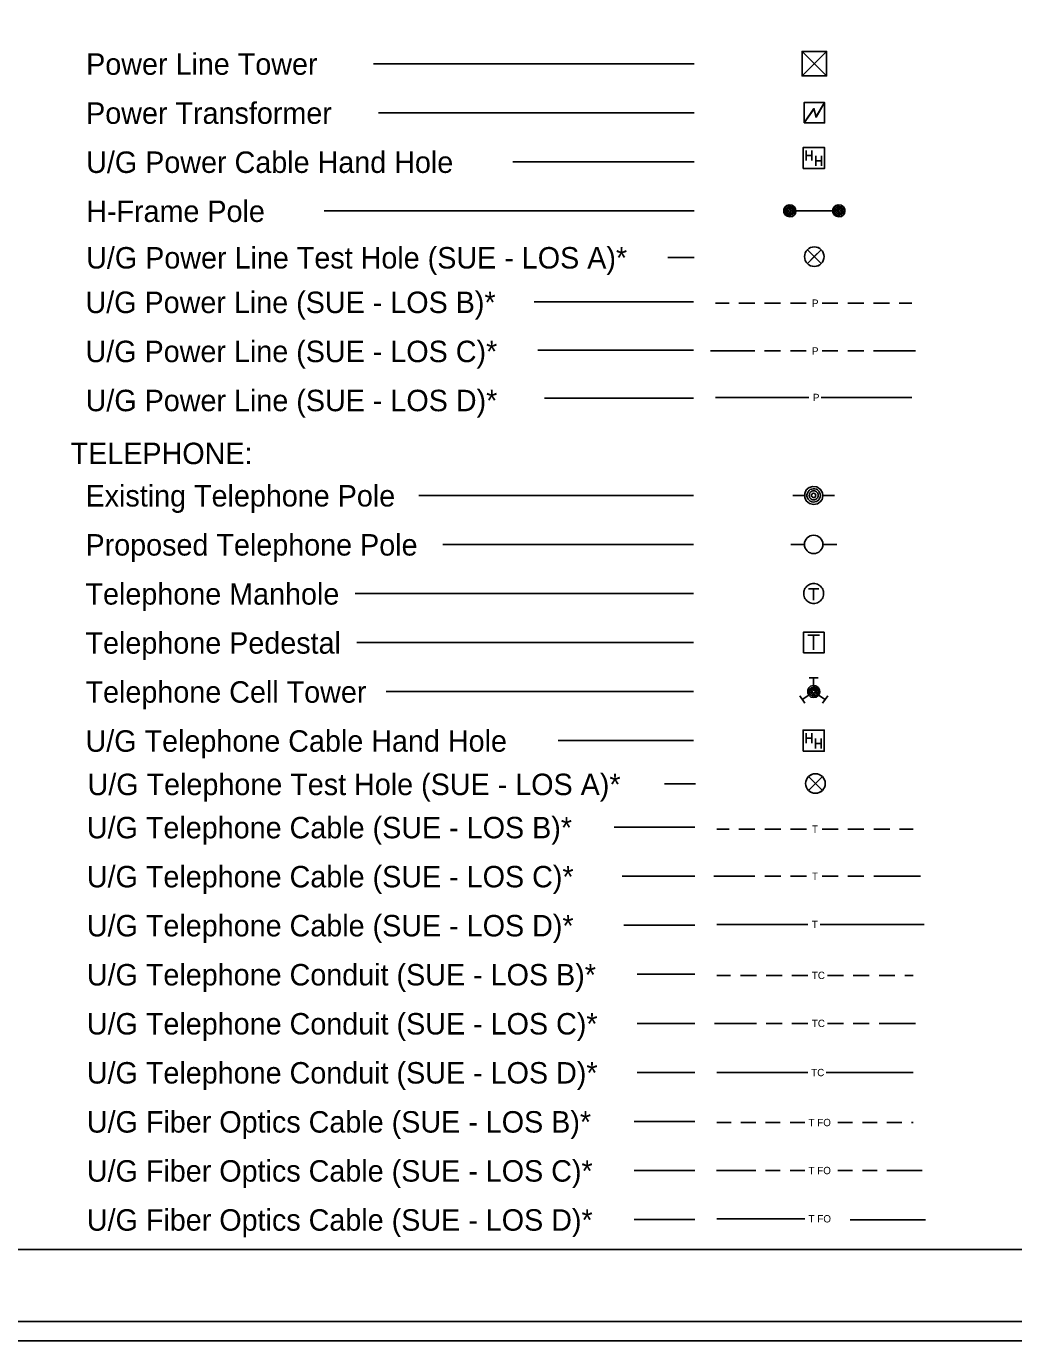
# Model space of a CAD drawing. Extents: x 811137 to 813186, y 647386 to 648494.
# Drawn here: x 812004 to 812410, y 647386 to 647927 of the extents above; entities that cross this region are included whole.
import ezdxf

# ---------------------------------------------------------------- set-up
doc = ezdxf.new("R2010")
doc.units = 0
for name, color, linetype in [('Default', 7, 'Continuous'), ('Exist Utilities Power Test Hole SUE LOS A CELL', 7, 'Continuous'), ('Exist Utilities Telephone Test Hole SUE LOS A CELL', 7, 'Continuous'), ('Sheet_Plan', 7, 'Continuous'), ('Sheet_Symbology', 7, 'Continuous'), ('z - Construction', 7, 'Continuous')]:
    doc.layers.add(name, color=color, linetype=linetype)

msp = doc.modelspace()

# ---------------------------------------------------------------- linework, layer by layer
at = {"layer": 'Default'}
msp.add_lwpolyline([(812820.63, 648494.02), (811136.63, 648494.02), (811136.63, 647394.02), (812820.63, 647394.02)], close=True, dxfattribs=at)
at = {"layer": 'Exist Utilities Power Test Hole SUE LOS A CELL'}
for points in [[(812330.92, 647834.94), (812325.21, 647829.24), (812328.07, 647832.09), (812325.21, 647834.94), (812330.92, 647829.24)], [(812325.21, 647834.94), (812328.07, 647832.09), (812330.92, 647834.94)], [(812330.92, 647829.24), (812328.07, 647832.09), (812325.21, 647829.24)]]:
    msp.add_lwpolyline(points, dxfattribs=at)
msp.add_circle((812328.07, 647832.09), 4.03, dxfattribs=at)
for start, end in [(45, 135), (225, 315)]:
    msp.add_arc((812328.07, 647832.09), 4.03, start, end, dxfattribs=at)
at = {"layer": 'Exist Utilities Telephone Test Hole SUE LOS A CELL'}
for points in [[(812331.39, 647618.17), (812325.69, 647612.47), (812328.54, 647615.32), (812325.69, 647618.17), (812331.39, 647612.47)], [(812325.69, 647618.17), (812328.54, 647615.32), (812331.39, 647618.17)], [(812331.39, 647612.47), (812328.54, 647615.32), (812325.69, 647612.47)]]:
    msp.add_lwpolyline(points, dxfattribs=at)
msp.add_circle((812328.54, 647615.32), 4.03, dxfattribs=at)
for start, end in [(45, 135), (225, 315)]:
    msp.add_arc((812328.54, 647615.32), 4.03, start, end, dxfattribs=at)
at = {"layer": 'Sheet_Plan'}
msp.add_line((811178.28, 647423.58), (812803.25, 647423.58), dxfattribs=at)
at = {"layer": 'Sheet_Symbology'}
for p, q in [((812333.15, 647916.53), (812323.08, 647906.45)), ((812333.15, 647906.45), (812323.08, 647916.53)), ((812278.64, 647911.46), (812146.8, 647911.46)), ((812278.64, 647891.28), (812148.85, 647891.28)), ((812324.79, 647875.74), (812324.79, 647871.67)), ((812327.11, 647875.74), (812327.11, 647871.67)), ((812278.64, 647871.1), (812204.09, 647871.1)), ((812324.79, 647873.66), (812327.11, 647873.66)), ((812328.67, 647873.52), (812328.67, 647869.46)), ((812328.67, 647871.45), (812330.99, 647871.45)), ((812330.99, 647873.52), (812330.99, 647869.46)), ((812278.64, 647850.93), (812126.6, 647850.93)), ((812318, 647850.93), (812338.18, 647850.93)), ((812278.64, 647831.78), (812267.91, 647831.78)), ((812278.36, 647813.45), (812212.86, 647813.45)), ((812287.46, 647812.96), (812293.01, 647812.96)), ((812297.04, 647812.96), (812303.6, 647812.96)), ((812307.64, 647812.96), (812314.19, 647812.96)), ((812318.23, 647812.96), (812324.79, 647812.96)), ((812331.24, 647812.96), (812337.8, 647812.96)), ((812341.84, 647812.96), (812348.4, 647812.96)), ((812352.43, 647812.96), (812358.99, 647812.96)), ((812363.03, 647812.96), (812368.17, 647812.96)), ((812278.36, 647793.66), (812214.42, 647793.66)), ((812285.42, 647793.27), (812303.6, 647793.27)), ((812307.64, 647793.27), (812314.19, 647793.27)), ((812318.23, 647793.27), (812324.79, 647793.27)), ((812331.24, 647793.27), (812337.8, 647793.27)), ((812341.84, 647793.27), (812348.4, 647793.27)), ((812352.43, 647793.27), (812369.61, 647793.27)), ((812278.36, 647773.86), (812217.13, 647773.86)), ((812287.46, 647774.14), (812325.88, 647774.14)), ((812330.93, 647774.14), (812368.17, 647774.14)), ((812278.36, 647733.86), (812165.48, 647733.86)), ((812324.09, 647733.86), (812319.25, 647733.86)), ((812331.54, 647733.86), (812336.38, 647733.86)), ((812278.36, 647713.68), (812175.39, 647713.68)), ((812324.07, 647713.67), (812318.39, 647713.67)), ((812331.64, 647713.67), (812337.31, 647713.67)), ((812278.36, 647693.5), (812139.27, 647693.5)), ((812329.91, 647695.4), (812325.75, 647695.4)), ((812327.81, 647695.4), (812327.81, 647690.81)), ((812325.45, 647676.36), (812330.17, 647676.36)), ((812327.81, 647670.28), (812327.81, 647676.36)), ((812278.36, 647673.32), (812139.97, 647673.32)), ((812325.92, 647658.85), (812329.71, 647658.85)), ((812327.81, 647655.63), (812327.81, 647658.85)), ((812278.36, 647653.14), (812152.02, 647653.14)), ((812324.23, 647648.32), (812322.06, 647651.42)), ((812325.79, 647651.72), (812323.14, 647649.87)), ((812329.85, 647651.73), (812332.49, 647649.88)), ((812333.58, 647651.43), (812331.41, 647648.33)), ((812278.36, 647632.97), (812222.83, 647632.97)), ((812324.72, 647636.02), (812324.72, 647631.95)), ((812324.72, 647633.95), (812327.04, 647633.95)), ((812327.04, 647636.02), (812327.04, 647631.95)), ((812328.6, 647633.8), (812328.6, 647629.74)), ((812330.93, 647633.8), (812330.93, 647629.74)), ((812328.6, 647631.73), (812330.93, 647631.73)), ((812279.19, 647615.13), (812266.42, 647615.13)), ((812278.91, 647597.35), (812245.84, 647597.35)), ((812288.01, 647596.55), (812293.08, 647596.55)), ((812297.11, 647596.55), (812303.67, 647596.55)), ((812307.71, 647596.55), (812314.27, 647596.55)), ((812318.3, 647596.55), (812324.86, 647596.55)), ((812331.32, 647596.55), (812337.87, 647596.55)), ((812341.91, 647596.55), (812348.47, 647596.55)), ((812352.5, 647596.55), (812359.06, 647596.55)), ((812363.1, 647596.55), (812368.72, 647596.55)), ((812278.91, 647577.17), (812249.03, 647577.17)), ((812286.75, 647577.17), (812303.67, 647577.17)), ((812307.71, 647577.17), (812314.27, 647577.17)), ((812318.3, 647577.17), (812324.86, 647577.17)), ((812331.32, 647577.17), (812337.87, 647577.17)), ((812341.91, 647577.17), (812348.47, 647577.17)), ((812352.5, 647577.17), (812371.71, 647577.17)), ((812278.91, 647556.99), (812249.8, 647556.99)), ((812288.01, 647557.35), (812325.46, 647557.35)), ((812330.51, 647557.35), (812373.27, 647557.35)), ((812278.91, 647536.82), (812255.24, 647536.82)), ((812288.01, 647536.38), (812293.64, 647536.38)), ((812297.68, 647536.38), (812304.24, 647536.38)), ((812308.27, 647536.38), (812314.83, 647536.38)), ((812318.87, 647536.38), (812325.43, 647536.38)), ((812333.5, 647536.38), (812340.06, 647536.38)), ((812344.09, 647536.38), (812350.65, 647536.38)), ((812354.69, 647536.38), (812361.24, 647536.38)), ((812365.28, 647536.38), (812368.72, 647536.38)), ((812278.91, 647516.64), (812255.24, 647516.64)), ((812287.05, 647516.64), (812304.24, 647516.64)), ((812308.27, 647516.64), (812314.83, 647516.64)), ((812318.87, 647516.64), (812325.43, 647516.64)), ((812333.5, 647516.64), (812340.06, 647516.64)), ((812344.09, 647516.64), (812350.65, 647516.64)), ((812354.69, 647516.64), (812369.69, 647516.64)), ((812278.91, 647496.46), (812255.24, 647496.46)), ((812288.01, 647496.41), (812325.43, 647496.41)), ((812332.99, 647496.41), (812368.72, 647496.41)), ((812278.91, 647476.28), (812254.07, 647476.28)), ((812288.01, 647475.84), (812293.9, 647475.84)), ((812297.93, 647475.84), (812303.99, 647475.84)), ((812308.02, 647475.84), (812314.08, 647475.84)), ((812318.11, 647475.84), (812324.17, 647475.84)), ((812337.79, 647475.84), (812343.84, 647475.84)), ((812347.88, 647475.84), (812353.93, 647475.84)), ((812357.96, 647475.84), (812364.02, 647475.84)), ((812368.05, 647475.84), (812368.72, 647475.84)), ((812278.91, 647456.1), (812254.07, 647456.1)), ((812287.82, 647456.1), (812303.99, 647456.1)), ((812308.02, 647456.1), (812314.08, 647456.1)), ((812318.11, 647456.1), (812324.17, 647456.1)), ((812337.79, 647456.1), (812343.84, 647456.1)), ((812347.88, 647456.1), (812353.93, 647456.1)), ((812357.96, 647456.1), (812372.41, 647456.1)), ((812278.91, 647435.92), (812254.07, 647435.92)), ((812288.01, 647436.25), (812324.2, 647436.25)), ((812342.87, 647435.86), (812373.77, 647435.86))]:
    msp.add_line(p, q, dxfattribs=at)
for points in [[(812333.15, 647906.45), (812323.08, 647906.45), (812323.08, 647916.53), (812333.15, 647916.53), (812333.15, 647906.45), (812323.08, 647906.45), (812323.08, 647916.53), (812333.15, 647916.53), (812333.15, 647906.45)], [(812323.88, 647887.08), (812327.86, 647892.79), (812328.82, 647889.68), (812332.29, 647895.49)], [(812323.88, 647887.08), (812327.89, 647893.02), (812328.79, 647889.45), (812332.29, 647895.49)], [(812323.88, 647887.08), (812332.29, 647887.08), (812332.29, 647895.49), (812323.88, 647895.49), (812323.88, 647887.08)], [(812323.54, 647868.34), (812332.22, 647868.34), (812332.22, 647877.03), (812323.54, 647877.03), (812323.54, 647868.34)], [(812319.84, 647850.93), (812319.79, 647851.37), (812319.64, 647851.77), (812319.39, 647852.12), (812319.09, 647852.41), (812318.75, 647852.61), (812318.3, 647852.71), (812317.9, 647852.76), (812317.45, 647852.66), (812317.06, 647852.51), (812316.76, 647852.27), (812316.46, 647851.92), (812316.26, 647851.57), (812316.16, 647851.12), (812316.16, 647850.73), (812316.26, 647850.28), (812316.46, 647849.93), (812316.76, 647849.58), (812317.06, 647849.34), (812317.45, 647849.19), (812317.9, 647849.09), (812318.3, 647849.14), (812318.75, 647849.24), (812319.09, 647849.44), (812319.39, 647849.73), (812319.64, 647850.08), (812319.79, 647850.48), (812319.84, 647850.93)], [(812319.24, 647850.93), (812319.19, 647851.27), (812319.04, 647851.62), (812318.79, 647851.87), (812318.5, 647852.07), (812318.2, 647852.17), (812317.8, 647852.17), (812317.5, 647852.07), (812317.21, 647851.87), (812316.96, 647851.62), (812316.81, 647851.27), (812316.76, 647850.93), (812316.81, 647850.58), (812316.96, 647850.23), (812317.21, 647849.98), (812317.5, 647849.78), (812317.8, 647849.68), (812318.2, 647849.68), (812318.5, 647849.78), (812318.79, 647849.98), (812319.04, 647850.23), (812319.19, 647850.58), (812319.24, 647850.93)], [(812318.6, 647850.93), (812318.55, 647851.17), (812318.4, 647851.37), (812318.2, 647851.47), (812317.95, 647851.52), (812317.7, 647851.42), (812317.5, 647851.27), (812317.4, 647851.03), (812317.4, 647850.83), (812317.5, 647850.58), (812317.7, 647850.43), (812317.95, 647850.33), (812318.2, 647850.38), (812318.4, 647850.48), (812318.55, 647850.68), (812318.6, 647850.93)], [(812340.02, 647850.93), (812339.97, 647851.37), (812339.82, 647851.77), (812339.57, 647852.12), (812339.27, 647852.41), (812338.92, 647852.61), (812338.48, 647852.71), (812338.08, 647852.76), (812337.63, 647852.66), (812337.24, 647852.51), (812336.94, 647852.27), (812336.64, 647851.92), (812336.44, 647851.57), (812336.34, 647851.12), (812336.34, 647850.73), (812336.44, 647850.28), (812336.64, 647849.93), (812336.94, 647849.58), (812337.24, 647849.34), (812337.63, 647849.19), (812338.08, 647849.09), (812338.48, 647849.14), (812338.92, 647849.24), (812339.27, 647849.44), (812339.57, 647849.73), (812339.82, 647850.08), (812339.97, 647850.48), (812340.02, 647850.93)], [(812339.42, 647850.93), (812339.37, 647851.27), (812339.22, 647851.62), (812338.97, 647851.87), (812338.68, 647852.07), (812338.38, 647852.17), (812337.98, 647852.17), (812337.68, 647852.07), (812337.38, 647851.87), (812337.14, 647851.62), (812336.99, 647851.27), (812336.94, 647850.93), (812336.99, 647850.58), (812337.14, 647850.23), (812337.38, 647849.98), (812337.68, 647849.78), (812337.98, 647849.68), (812338.38, 647849.68), (812338.68, 647849.78), (812338.97, 647849.98), (812339.22, 647850.23), (812339.37, 647850.58), (812339.42, 647850.93)], [(812338.77, 647850.93), (812338.73, 647851.17), (812338.58, 647851.37), (812338.38, 647851.47), (812338.13, 647851.52), (812337.88, 647851.42), (812337.68, 647851.27), (812337.58, 647851.03), (812337.58, 647850.83), (812337.68, 647850.58), (812337.88, 647850.43), (812338.13, 647850.33), (812338.38, 647850.38), (812338.58, 647850.48), (812338.73, 647850.68), (812338.77, 647850.93)], [(812330.57, 647733.86), (812330.49, 647734.53), (812330.27, 647735.12), (812329.9, 647735.65), (812329.45, 647736.09), (812328.93, 647736.39), (812328.26, 647736.54), (812327.66, 647736.62), (812326.99, 647736.47), (812326.4, 647736.24), (812325.95, 647735.87), (812325.51, 647735.35), (812325.21, 647734.83), (812325.06, 647734.16), (812325.06, 647733.56), (812325.21, 647732.89), (812325.51, 647732.37), (812325.95, 647731.85), (812326.4, 647731.48), (812326.99, 647731.25), (812327.66, 647731.1), (812328.26, 647731.18), (812328.93, 647731.33), (812329.45, 647731.63), (812329.9, 647732.07), (812330.27, 647732.59), (812330.49, 647733.19), (812330.57, 647733.86)], [(812329.68, 647733.86), (812329.6, 647734.38), (812329.38, 647734.9), (812329.01, 647735.27), (812328.56, 647735.57), (812328.11, 647735.72), (812327.52, 647735.72), (812327.07, 647735.57), (812326.62, 647735.27), (812326.25, 647734.9), (812326.03, 647734.38), (812325.95, 647733.86), (812326.03, 647733.34), (812326.25, 647732.82), (812326.62, 647732.44), (812327.07, 647732.15), (812327.52, 647732), (812328.11, 647732), (812328.56, 647732.15), (812329.01, 647732.44), (812329.38, 647732.82), (812329.6, 647733.34), (812329.68, 647733.86)], [(812328.71, 647733.86), (812328.63, 647734.23), (812328.41, 647734.53), (812328.11, 647734.68), (812327.74, 647734.75), (812327.37, 647734.6), (812327.07, 647734.38), (812326.92, 647734.01), (812326.92, 647733.71), (812327.07, 647733.34), (812327.37, 647733.11), (812327.74, 647732.97), (812328.11, 647733.04), (812328.41, 647733.19), (812328.63, 647733.49), (812328.71, 647733.86)], [(812327.81, 647697.6), (812327.29, 647697.56), (812326.8, 647697.47), (812326.31, 647697.3), (812325.85, 647697.07), (812325.42, 647696.81), (812325.03, 647696.48), (812324.67, 647696.09), (812324.37, 647695.7), (812324.11, 647695.24), (812323.95, 647694.75), (812323.82, 647694.26), (812323.75, 647693.76), (812323.75, 647693.24), (812323.82, 647692.75), (812323.95, 647692.22), (812324.11, 647691.76), (812324.37, 647691.31), (812324.67, 647690.91), (812325.03, 647690.52), (812325.42, 647690.19), (812325.85, 647689.93), (812326.31, 647689.7), (812326.8, 647689.54), (812327.32, 647689.44), (812327.81, 647689.41), (812328.34, 647689.44), (812328.83, 647689.54), (812329.32, 647689.7), (812329.78, 647689.93), (812330.21, 647690.19), (812330.6, 647690.52), (812330.96, 647690.91), (812331.26, 647691.31), (812331.52, 647691.76), (812331.68, 647692.26), (812331.81, 647692.75), (812331.88, 647693.24), (812331.88, 647693.76), (812331.81, 647694.26), (812331.68, 647694.78), (812331.52, 647695.24), (812331.26, 647695.7), (812330.96, 647696.09), (812330.6, 647696.48), (812330.21, 647696.81), (812329.78, 647697.07), (812329.32, 647697.3), (812328.83, 647697.47), (812328.31, 647697.56), (812327.81, 647697.6)], [(812323.57, 647669.08), (812332.06, 647669.08), (812332.06, 647677.57), (812323.57, 647677.57), (812323.57, 647669.08)], [(812329.65, 647653.14), (812329.6, 647653.59), (812329.45, 647653.99), (812329.2, 647654.34), (812328.91, 647654.63), (812328.56, 647654.83), (812328.11, 647654.93), (812327.71, 647654.98), (812327.27, 647654.88), (812326.87, 647654.73), (812326.57, 647654.48), (812326.28, 647654.14), (812326.08, 647653.79), (812325.98, 647653.34), (812325.98, 647652.95), (812326.08, 647652.5), (812326.28, 647652.15), (812326.57, 647651.8), (812326.87, 647651.56), (812327.27, 647651.41), (812327.71, 647651.31), (812328.11, 647651.36), (812328.56, 647651.45), (812328.91, 647651.66), (812329.2, 647651.95), (812329.45, 647652.3), (812329.6, 647652.7), (812329.65, 647653.14)], [(812329.05, 647653.14), (812329.01, 647653.49), (812328.86, 647653.84), (812328.61, 647654.09), (812328.31, 647654.29), (812328.01, 647654.38), (812327.62, 647654.38), (812327.32, 647654.29), (812327.02, 647654.09), (812326.77, 647653.84), (812326.62, 647653.49), (812326.57, 647653.14), (812326.62, 647652.8), (812326.77, 647652.45), (812327.02, 647652.2), (812327.32, 647652), (812327.62, 647651.9), (812328.01, 647651.9), (812328.31, 647652), (812328.61, 647652.2), (812328.86, 647652.45), (812329.01, 647652.8), (812329.05, 647653.14)], [(812328.41, 647653.14), (812328.36, 647653.39), (812328.21, 647653.59), (812328.01, 647653.69), (812327.76, 647653.74), (812327.52, 647653.64), (812327.32, 647653.49), (812327.22, 647653.24), (812327.22, 647653.04), (812327.32, 647652.8), (812327.52, 647652.65), (812327.76, 647652.55), (812328.01, 647652.6), (812328.21, 647652.7), (812328.36, 647652.9), (812328.41, 647653.14)], [(812323.47, 647628.62), (812332.16, 647628.62), (812332.16, 647637.31), (812323.47, 647637.31), (812323.47, 647628.62)]]:
    msp.add_lwpolyline(points, dxfattribs=at)
for points in [[(812318, 647848.44), (812319.04, 647848.64), (812319.74, 647849.14), (812320.28, 647849.83), (812320.48, 647850.78), (812320.38, 647851.67), (812319.89, 647852.56), (812318.89, 647853.31), (812317.75, 647853.41), (812316.76, 647853.11), (812315.96, 647852.41), (812315.57, 647851.47), (812315.57, 647850.38), (812315.96, 647849.44), (812316.86, 647848.69)], [(812338.18, 647848.44), (812339.22, 647848.64), (812339.92, 647849.14), (812340.46, 647849.83), (812340.66, 647850.78), (812340.56, 647851.67), (812340.07, 647852.56), (812339.07, 647853.31), (812337.93, 647853.41), (812336.94, 647853.11), (812336.14, 647852.41), (812335.75, 647851.47), (812335.75, 647850.38), (812336.14, 647849.44), (812337.04, 647848.69)], [(812327.81, 647730.13), (812329.38, 647730.43), (812330.42, 647731.18), (812331.24, 647732.22), (812331.54, 647733.63), (812331.39, 647734.98), (812330.65, 647736.32), (812329.16, 647737.43), (812327.44, 647737.58), (812325.95, 647737.14), (812324.76, 647736.09), (812324.17, 647734.68), (812324.17, 647733.04), (812324.76, 647731.63), (812326.1, 647730.51)], [(812327.81, 647650.66), (812328.86, 647650.86), (812329.55, 647651.36), (812330.1, 647652.05), (812330.3, 647652.99), (812330.2, 647653.89), (812329.7, 647654.78), (812328.71, 647655.53), (812327.57, 647655.63), (812326.57, 647655.33), (812325.78, 647654.63), (812325.38, 647653.69), (812325.38, 647652.6), (812325.78, 647651.66), (812326.67, 647650.91)]]:
    msp.add_lwpolyline(points, close=True, dxfattribs=at)
msp.add_circle((812327.81, 647713.68), 3.78, dxfattribs=at)
at = {"layer": 'z - Construction'}
msp.add_line((811140.78, 647386.08), (812840.77, 647386.08), dxfattribs=at)

# ---------------------------------------------------------------- texts
at = {"layer": 'Sheet_Symbology'}
for s, height, p in [('Power Line Tower', 8.8282, (812028.7, 647906.9)), ('Power Transformer', 8.8282, (812028.69, 647886.72)), ('U/G Power Cable Hand Hole', 8.8282, (812028.71, 647866.53)), ('H-Frame Pole', 8.8282, (812028.71, 647846.35)), ('U/G Power Line Test Hole (SUE - LOS A)*', 8.8282, (812028.71, 647827.2)), ('U/G Power Line (SUE - LOS B)*', 8.8282, (812028.44, 647808.87)), ('P', 3.03, (812327.11, 647811.44)), ('U/G Power Line (SUE - LOS C)*', 8.8282, (812028.46, 647788.68)), ('P', 3.03, (812327.11, 647791.76)), ('U/G Power Line (SUE - LOS D)*', 8.8282, (812028.49, 647768.49)), ('P', 3.03, (812327.5, 647772.63)), ('TELEPHONE:', 8.828, (812022.32, 647746.72)), ('Existing Telephone Pole', 8.8282, (812028.44, 647729.28)), ('Proposed Telephone Pole', 8.8282, (812028.44, 647709.1)), ('Telephone Manhole', 8.8282, (812028.44, 647688.92)), ('Telephone Pedestal', 8.8282, (812028.44, 647668.74)), ('Telephone Cell Tower', 8.8282, (812028.45, 647648.57)), ('U/G Telephone Cable Hand Hole', 8.8282, (812028.45, 647628.39)), ('U/G Telephone Test Hole (SUE - LOS A)*', 8.8282, (812029.28, 647610.55)), ('U/G Telephone Cable (SUE - LOS B)*', 8.8282, (812029, 647592.77)), ('T', 3.03, (812327.13, 647595.03)), ('U/G Telephone Cable (SUE - LOS C)*', 8.8282, (812029, 647572.59)), ('T', 3.03, (812327.13, 647575.66)), ('U/G Telephone Cable (SUE - LOS D)*', 8.8282, (812029, 647552.42)), ('T', 3.03, (812327.03, 647555.83)), ('U/G Telephone Conduit (SUE - LOS B)*', 8.8282, (812029, 647532.24)), ('TC', 3.027, (812327.04, 647534.87)), ('U/G Telephone Conduit (SUE - LOS C)*', 8.8282, (812029, 647512.06)), ('TC', 3.027, (812327.04, 647515.12)), ('U/G Telephone Conduit (SUE - LOS D)*', 8.8282, (812029, 647491.88)), ('TC', 3.027, (812326.79, 647494.9)), ('U/G Fiber Optics Cable (SUE - LOS B)*', 8.8282, (812029, 647471.7)), ('T FO', 3.027, (812325.68, 647474.33)), ('U/G Fiber Optics Cable (SUE - LOS C)*', 8.8282, (812029, 647451.52)), ('T FO', 3.027, (812325.68, 647454.59)), ('U/G Fiber Optics Cable (SUE - LOS D)*', 8.8282, (812029, 647431.34)), ('T FO', 3.027, (812325.72, 647434.74))]:
    msp.add_text(s, height=height, dxfattribs=at).set_placement(p)

doc.saveas('drawing.dxf')
